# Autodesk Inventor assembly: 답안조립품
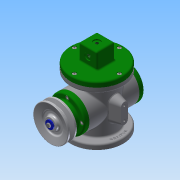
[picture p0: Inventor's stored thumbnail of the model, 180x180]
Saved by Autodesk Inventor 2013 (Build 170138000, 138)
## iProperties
Created: 2018-02
Part Number: 답안조립품
Document SubType Name: Assembly
Designer: Administrator
Author: Administrator
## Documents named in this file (18)
- C:\Users\Administrator\Desktop\480208V1011\답안조립품.iam
- C:\Users\Administrator\Desktop\480208V1011\본체 1.ipt
- C:\Users\Administrator\Desktop\480208V1011\E-링.ipt
- C:\Users\Administrator\Desktop\480208V1011\V-벨트풀리.ipt
- C:\Users\Administrator\Desktop\480208V1011\덮개.ipt
- C:\Users\Administrator\Desktop\480208V1011\뒤커버.ipt
- C:\Users\Administrator\Desktop\480208V1011\링크.ipt
- C:\Users\Administrator\Desktop\480208V1011\베어링 17 x 40 x 12.ipt
- C:\Users\Administrator\Desktop\480208V1011\볼트 M4 x 8.ipt
- C:\Users\Administrator\Desktop\480208V1011\볼트 M4 x 10.ipt
- C:\Users\Administrator\Desktop\480208V1011\슬라이더.ipt
- C:\Users\Administrator\Desktop\480208V1011\앞커버.ipt
- C:\Users\Administrator\Desktop\480208V1011\오일 실 17 30 8.ipt
- C:\Users\Administrator\Desktop\480208V1011\와셔 4x16.ipt
- C:\Users\Administrator\Desktop\480208V1011\클레비스 핀 6 x 22.ipt
- 클레비스 핀 6 x 22.ipt
- C:\Users\Administrator\Desktop\480208V1011\키 4 x 4 x 12.ipt
- C:\Users\Administrator\Desktop\480208V1011\편심축.ipt
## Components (2 placed, 2 different names)
1. E-링:1
2. V-벨트풀리:1
